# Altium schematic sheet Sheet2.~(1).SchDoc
size A4; SheetNumber: 1; SheetTotal: 1
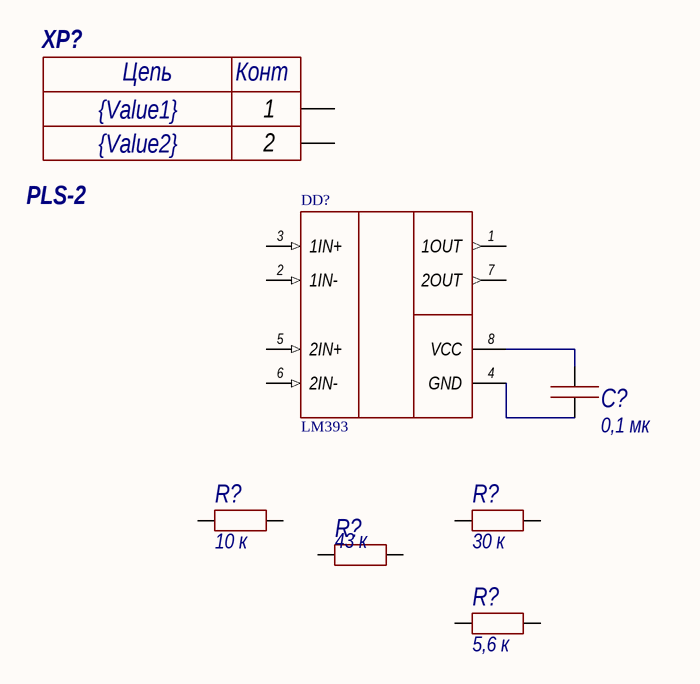
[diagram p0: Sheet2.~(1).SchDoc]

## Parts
(Parts that share a designator on the sheet are numbered #1, #2 ... from top to bottom, then left to right.)
C?  value 0,1 мк  [0603C]  (hidden comment: Capacitor)
DD?  LM393  [SOIC-8]
R?#1  value 10 к  [0603R]  (hidden comment: Resistor)
R?#2  value 30 к  [0603R]  (hidden comment: Resistor)
R?#3  value 43 к  [0603R]  (hidden comment: Resistor)
R?#4  value 5,6 к  [0603R]  (hidden comment: Resistor)
XP?  PLS-2  Value2: {Value2}  Value1: {Value1}  [PLS2]

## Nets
NetC?_1: C?.1 DD?.4(GND)
NetC?_2: C?.2 DD?.8(VCC)

Not connected (* = marked no-connect by the designer): DD? 1(1OUT) 2(1IN-) 3(1IN+) 5(2IN+) 6(2IN-) 7(2OUT); R?#1 1 2; R?#2 1 2; R?#3 1 2; R?#4 1 2; XP? 1 2

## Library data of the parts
C? = Capacitor_0,1u_10_50V_X7R_0603C: Конденсатор 0603C ёмкостью 0,1 мк 10%, 50 В, X7R; Library Path2: Schematic\Capacitor.SchLib; Voltage (V): 50; Capacity (nF): 100
DD? = LM393: Двойной маломощный компаратор напряжения; MF: Texas Instruments; MP: LM393D
R?#1 = Resistor_10k_1_0603: Резистор номиналом 10 кОм 1%
R?#2 = Resistor_30k_1_0603: Резистор номиналом 30 кОм 1%
R?#3 = Resistor_43k_1_0603: Резистор номиналом 43 кОм 1%
R?#4 = Resistor_5.6k_1_0603: Резистор номиналом 5,6 кОм 1%
XP? = PLS-2: Гребенка 2 пина; System: Connector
